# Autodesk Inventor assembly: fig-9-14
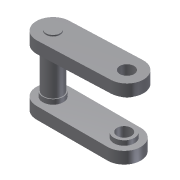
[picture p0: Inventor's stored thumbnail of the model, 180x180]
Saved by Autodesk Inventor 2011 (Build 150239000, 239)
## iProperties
Shininess: 64.0
Length Units: 11269
Angle Units: 11279
Time Units: 11290
Mass Units: 11283
Length Display Precision: 3
Angle Display Precision: 2
Created: 2002-01
Part Number: fig-9-14
Document SubType Name: Assembly
Designer: ***
Density: 0.0
Volumn: 0.0
Area: 0.0
PropertySet Name: Model Information
Control State: 0
Master: False
Checked Out: False
Author: ***
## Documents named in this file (3)
- C:\Users\CADSoft\Desktop\part files\c09-inv-2011-prt\fig-9-14.iam
- C:\Users\CADSoft\Desktop\inventor\c09-inv-2010-prt\c09\Part5.ipt
- C:\Users\CADSoft\Desktop\inventor\c09-inv-2010-prt\c09\Part6.ipt
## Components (3 placed, 2 different names)
1. Part5:1 — Insert:1
2. Part6:1 — Insert:1, Insert:2
3. Part5:2 — Insert:2
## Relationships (2: Insert 2)
- Insert:1: Part5:1 ↔ Part6:1
- Insert:2: Part6:1 ↔ Part5:2
